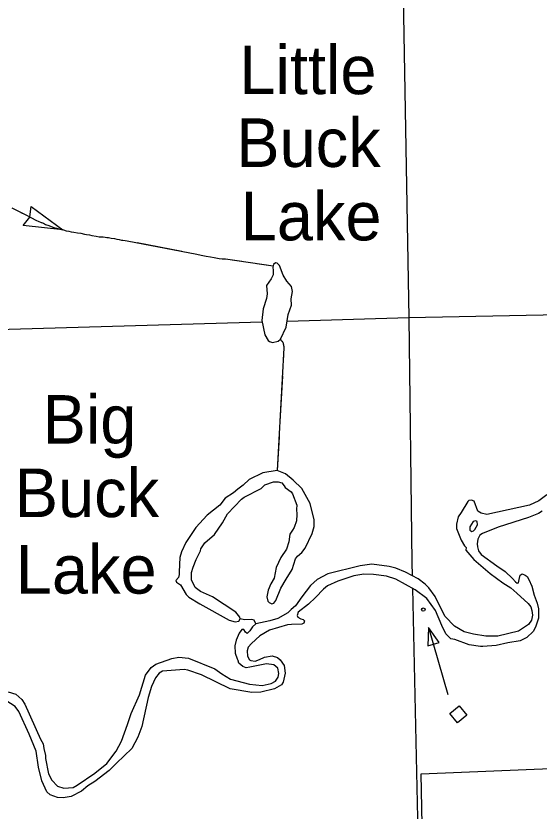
# Model space of a CAD drawing. Extents: x 1084508 to 1142749, y 1057638 to 1093403.
# Drawn here: x 1086600 to 1088029, y 1078847 to 1081018 of the extents above; entities that cross this region are included whole.
import ezdxf

# ---------------------------------------------------------------- set-up
doc = ezdxf.new("R2010")
doc.units = 0
for name, color, linetype in [('Level 35', 7, 'Continuous'), ('Level 43', 7, 'Continuous'), ('Level 5', 7, 'Continuous'), ('Level 56', 7, 'Continuous'), ('Level 7', 7, 'Continuous'), ('Level 9', 7, 'Continuous')]:
    doc.layers.add(name, color=color, linetype=linetype)

msp = doc.modelspace()

# ---------------------------------------------------------------- linework, layer by layer
at = {"layer": 'Level 35'}
for points in [[(1087303.2, 1080335.8), (1087301.5, 1080332), (1087302.5, 1080322.9), (1087302.4, 1080311.2), (1087296.9, 1080299.9), (1087284.8, 1080282.3), (1087286.5, 1080259.6), (1087284.5, 1080246.9), (1087275.8, 1080218.1), (1087272.2, 1080186.4), (1087279.6, 1080147.6), (1087288.8, 1080131.6), (1087292.7, 1080129.3), (1087300.7, 1080126.5), (1087316.3, 1080129.7), (1087322.6, 1080135.1)], [(1087322.6, 1080135.1), (1087338.4, 1080168.3), (1087343.8, 1080202.9), (1087353, 1080228), (1087351.6, 1080245.6), (1087355.5, 1080265.3), (1087352.9, 1080279.1), (1087340, 1080293.7), (1087330.1, 1080310.2), (1087320.1, 1080336.9), (1087313.9, 1080342.9), (1087308.8, 1080344), (1087303.7, 1080339), (1087303.2, 1080335.8)], [(1087313.9, 1079777.4), (1087274.6, 1079770.6), (1087237.6, 1079752.8), (1087220.8, 1079736.6), (1087206.1, 1079726.4), (1087194.6, 1079716.4), (1087171.4, 1079701.5), (1087156.8, 1079682.5), (1087122.5, 1079655.4), (1087091.9, 1079621.5), (1087064.5, 1079580.1), (1087052.1, 1079554.6), (1087048.4, 1079539.9), (1087045.8, 1079500.1), (1087046.1, 1079493.1), (1087044.6, 1079484.9), (1087037.4, 1079477), (1087038.9, 1079472), (1087049.9, 1079464.9), (1087065.5, 1079438.8), (1087072.5, 1079431.2)], [(1087338.7, 1079480.4), (1087354.5, 1079507), (1087363.9, 1079535.5), (1087369.2, 1079543.3), (1087380.7, 1079553.3), (1087390.2, 1079565.1), (1087409.5, 1079604.8), (1087415.2, 1079624), (1087415, 1079642.3), (1087403.9, 1079686.9), (1087380.7, 1079727.5), (1087357.6, 1079751), (1087336.1, 1079768), (1087313.9, 1079777.4)], [(1087223.5, 1079704.5), (1087269.6, 1079728.1), (1087279.9, 1079737.7), (1087303.4, 1079746), (1087316.9, 1079746.3), (1087326.5, 1079743), (1087333.1, 1079735.4), (1087335.9, 1079730.5), (1087351.8, 1079718.6), (1087355.8, 1079713.1), (1087367.3, 1079682.1), (1087366.5, 1079671.3), (1087367.8, 1079656.8), (1087366.1, 1079639.4), (1087360, 1079621.1), (1087355.3, 1079614.6), (1087348.2, 1079603.2), (1087345.4, 1079582), (1087339.4, 1079562.1), (1087323.4, 1079539.9), (1087311.4, 1079511.9), (1087305.2, 1079483.6), (1087296.4, 1079468), (1087289.1, 1079450), (1087285.8, 1079432.2), (1087288.5, 1079420.3), (1087291.8, 1079416.7), (1087299.2, 1079413.2), (1087304.2, 1079415), (1087310.4, 1079422.6), (1087324, 1079456), (1087338.7, 1079480.4)], [(1087255.5, 1079358.2), (1087250.9, 1079369), (1087244.8, 1079370.3), (1087224.7, 1079369.4), (1087212.7, 1079372), (1087212.1, 1079376.7), (1087200.8, 1079390.4), (1087137.6, 1079432), (1087104.8, 1079447.2), (1087089.9, 1079457.3), (1087080.1, 1079478.9), (1087079.8, 1079498.8), (1087084.2, 1079513.2), (1087092.4, 1079534.1), (1087104.5, 1079557.7), (1087105.2, 1079563.1), (1087116.4, 1079580), (1087142.5, 1079602.3), (1087164.3, 1079634.3), (1087178.3, 1079658.9), (1087216.5, 1079699.1), (1087223.5, 1079704.5)], [(1087072.5, 1079431.2), (1087102.3, 1079412.7), (1087182.3, 1079368.7), (1087198.6, 1079364.1), (1087208.9, 1079365.5), (1087212.7, 1079372)]]:
    msp.add_lwpolyline(points, dxfattribs=at)
at = {"layer": 'Level 43'}
for p, q in [((1086638.1, 1080469), (1086641.8, 1080497.4)), ((1086641.8, 1080497.7), (1086728.3, 1080433.7)), ((1086620.5, 1080445.8), (1086638, 1080468.6)), ((1086728.4, 1080433.7), (1086620.4, 1080445.8)), ((1086620.4, 1080445.8), (1086620.5, 1080445.8))]:
    msp.add_line(p, q, dxfattribs=at)
for points in [[(1086589.7, 1080494.3), (1086609.3, 1080483.6), (1086626.1, 1080475.5), (1086642.8, 1080466.5), (1086655.1, 1080460.4), (1086663.4, 1080456.7), (1086667.9, 1080454.4), (1086675.6, 1080451.9), (1086681.1, 1080448.7), (1086690, 1080445.6), (1086696.4, 1080443.4), (1086704.4, 1080440.6), (1086711.4, 1080438.4), (1086721.6, 1080435.4), (1086730.2, 1080433.6), (1086737.2, 1080431.4), (1086744.6, 1080429.8), (1086750.9, 1080428.8), (1086758.5, 1080427.3), (1086768.6, 1080425.9), (1086777.5, 1080424.4), (1086788, 1080421.7), (1086793.1, 1080421.3), (1086801.6, 1080419.8), (1086807.4, 1080418.2), (1086819.4, 1080416.2), (1086827.7, 1080414.7), (1086834.3, 1080414.4), (1086838.7, 1080414.6), (1086843.7, 1080414.2), (1086848.8, 1080413.4), (1086853.6, 1080412.7), (1086860.6, 1080410.8), (1086869.4, 1080410), (1086876.4, 1080408.1), (1086882.1, 1080407.1), (1086888.5, 1080406.1), (1086892.3, 1080406), (1086898.9, 1080404.7), (1086904.3, 1080404.3), (1087094.4, 1080367.6), (1087106.2, 1080365), (1087119.8, 1080362.4), (1087131.6, 1080360.1), (1087142, 1080358.7), (1087155.7, 1080355.9), (1087163.9, 1080355), (1087172.7, 1080354.8), (1087303.2, 1080335.8)], [(1086613.6, 1080481.5), (1086626.1, 1080475.5), (1086642.8, 1080466.5), (1086655.1, 1080460.4), (1086663.4, 1080456.7), (1086667.9, 1080454.4), (1086669.3, 1080453.9)], [(1086669.3, 1080453.9), (1086675.6, 1080451.9), (1086681.1, 1080448.7), (1086690, 1080445.6), (1086696.4, 1080443.4), (1086704.4, 1080440.6), (1086711.4, 1080438.4), (1086721.6, 1080435.4), (1086728, 1080434)], [(1086768.5, 1080425.9), (1086768.6, 1080425.9), (1086777.5, 1080424.4), (1086788, 1080421.7), (1086793.1, 1080421.3), (1086801.6, 1080419.8), (1086807.4, 1080418.2), (1086819.4, 1080416.2), (1086827.7, 1080414.7), (1086834.3, 1080414.4), (1086838.7, 1080414.6), (1086843.7, 1080414.2), (1086848.8, 1080413.4), (1086853.6, 1080412.7), (1086860.6, 1080410.8), (1086869.4, 1080410), (1086876.4, 1080408.1), (1086882.1, 1080407.1), (1086888.5, 1080406.1), (1086890.9, 1080406)], [(1086931.7, 1080399), (1087053.7, 1080375.5)], [(1087094.4, 1080367.6), (1087094.4, 1080367.6), (1087106.2, 1080365), (1087119.8, 1080362.4), (1087131.6, 1080360.1), (1087142, 1080358.7), (1087155.7, 1080355.9), (1087163.9, 1080355), (1087172.7, 1080354.8), (1087217, 1080348.3)], [(1087258, 1080342.4), (1087303.2, 1080335.8)], [(1087322.6, 1080135.1), (1087324, 1080133.6), (1087325, 1080132.3), (1087325, 1080132), (1087325.6, 1080131.4), (1087326.3, 1080130.2), (1087327.6, 1080129.6), (1087328.3, 1080128.1), (1087329, 1080126.8), (1087329.7, 1080125.3), (1087330.4, 1080122.8), (1087331.2, 1080120.3), (1087331.3, 1080118.4), (1087332, 1080115.3), (1087332.2, 1080111.5), (1087313.9, 1079777.4)], [(1087322.6, 1080135.1), (1087324, 1080133.6), (1087325, 1080132.3), (1087325, 1080132), (1087325.6, 1080131.4), (1087326.3, 1080130.2), (1087327.6, 1080129.6), (1087328.3, 1080128.1), (1087329, 1080126.8), (1087329.7, 1080125.3), (1087330.4, 1080122.8), (1087331.2, 1080120.3), (1087331.3, 1080118.4), (1087332, 1080115.3), (1087332.2, 1080111.5), (1087330.2, 1080075.9)], [(1087328, 1080034.6), (1087321.2, 1079910.4)], [(1087318.9, 1079869.1), (1087313.9, 1079777.4)]]:
    msp.add_lwpolyline(points, dxfattribs=at)
at = {"layer": 'Level 5'}
msp.add_line((1087273, 1080182.1), (1085752.4, 1080138.1), dxfattribs=at)
for points in [[(1087592.5, 1084319.5), (1087602.1, 1083492.6), (1087618.6, 1082806.7), (1087643.8, 1081844.1), (1087673, 1080193.7), (1087681.8, 1079526.1)], [(1088360.3, 1080207.8), (1087673, 1080193.7), (1087340.9, 1080184.1)], [(1087681.8, 1079526.1), (1087682.5, 1079490.6)], [(1087683.3, 1079455.6), (1087701.8, 1078618.5)]]:
    msp.add_lwpolyline(points, dxfattribs=at)
at = {"layer": 'Level 56'}
for points in [[(1087725, 1079298.3), (1087755.7, 1079307.2), (1087727, 1079348.8)], [(1087785.3, 1079113.6), (1087810.6, 1079134.3), (1087831.4, 1079108.9), (1087806.1, 1079088.2)]]:
    msp.add_lwpolyline(points, close=True, dxfattribs=at)
msp.add_lwpolyline([(1087727, 1079348.8), (1087780, 1079166)], dxfattribs=at)
msp.add_circle((1087712.8, 1079397.5), 4.71, dxfattribs=at)
at = {"layer": 'Level 7'}
msp.add_lwpolyline([(1087713.6, 1078624.6), (1087706.6, 1078948.8), (1088170.3, 1078968.6), (1088170.5, 1079039.2), (1088369.3, 1079043.8), (1088402, 1078976.5), (1088431.3, 1078977.5)], dxfattribs=at)
at = {"layer": 'Level 9'}
for points in [[(1088050.4, 1079710.2), (1088028.1, 1079694.7), (1088002.8, 1079682.8), (1087886.4, 1079656.6), (1087871.1, 1079661), (1087862, 1079666.3), (1087851.3, 1079693.5), (1087844.3, 1079696.4), (1087837.4, 1079694.8), (1087834.4, 1079692.1), (1087816.3, 1079662.3), (1087808, 1079650.8), (1087803.2, 1079630.7), (1087803.7, 1079618.8), (1087815.9, 1079586.5), (1087825.4, 1079571.2), (1087830, 1079567), (1087829.1, 1079560), (1087850.7, 1079534.5), (1087894.9, 1079496.1), (1087930, 1079470.6), (1087952, 1079456.4), (1087967.8, 1079442), (1087999.2, 1079414.4), (1088006.3, 1079404.6), (1088008.9, 1079394.7)], [(1088037, 1079666.1), (1088027.2, 1079659.3), (1088000, 1079648.6), (1087916.9, 1079622.1), (1087874.2, 1079604.7), (1087867.5, 1079600.2), (1087861.7, 1079589.9), (1087859.7, 1079577.2), (1087860.5, 1079568.4), (1087863.1, 1079557.8), (1087870.5, 1079547.4), (1087913.4, 1079517.1), (1087936.1, 1079501.8), (1087956.5, 1079482.2), (1087964.5, 1079473.4), (1087969, 1079469.8), (1087972.2, 1079470), (1087974.9, 1079479.6), (1087977.5, 1079491.7), (1087982.4, 1079494.7), (1087991, 1079491.7), (1087996.3, 1079487.5), (1088000.7, 1079479.8)], [(1087853.3, 1079615.7), (1087860.9, 1079628.3), (1087859.6, 1079637.8), (1087856.3, 1079640.1), (1087848.9, 1079637.7), (1087839.8, 1079623), (1087839.8, 1079614.4), (1087845.6, 1079610.9), (1087850, 1079612.1), (1087853.3, 1079615.7)], [(1088008.9, 1079394.7), (1088010.8, 1079382.1), (1088008.2, 1079368.8), (1087999.6, 1079357), (1087986.5, 1079347.6), (1087972.4, 1079338.7), (1087916.1, 1079324.8), (1087883.7, 1079325.2), (1087849.5, 1079330.5), (1087824.6, 1079337), (1087798.2, 1079352.2), (1087772.4, 1079378.8), (1087759, 1079404.7), (1087745.4, 1079433.1), (1087728, 1079457.2), (1087717.5, 1079467.1), (1087698.9, 1079481.1), (1087664.4, 1079499.4), (1087637.5, 1079510.2), (1087619.9, 1079515.4), (1087572.2, 1079521.1), (1087540.3, 1079517.1), (1087451.9, 1079494.7), (1087422.7, 1079479.5), (1087404.6, 1079462.9), (1087380.8, 1079432.1), (1087364, 1079408), (1087351.9, 1079397.3), (1087342.8, 1079389)], [(1088000.7, 1079479.8), (1088009.1, 1079461.6), (1088015.2, 1079437.2), (1088023.8, 1079414.9), (1088027.3, 1079399.3), (1088026.9, 1079374), (1088019.5, 1079349.1), (1088012.8, 1079337.7), (1087995.3, 1079321.1), (1087976.8, 1079311.8), (1087943.7, 1079307.1), (1087911.9, 1079299.3), (1087875.5, 1079297), (1087869.3, 1079296.7), (1087838.2, 1079301.6), (1087799.2, 1079315.6), (1087787.5, 1079317.6), (1087773.9, 1079331.5), (1087763.5, 1079354.4), (1087746.2, 1079394.9), (1087722.4, 1079427.6), (1087690.5, 1079451.4), (1087637.3, 1079480.5), (1087612.7, 1079488.2), (1087576.6, 1079493.5), (1087550.4, 1079494.2), (1087522.6, 1079489.4), (1087479.5, 1079475.1), (1087451.5, 1079461.9), (1087440.6, 1079453.2)], [(1087440.6, 1079453.2), (1087418, 1079430.7), (1087399, 1079412.1), (1087371, 1079390.6), (1087368.3, 1079381.7), (1087370.4, 1079377), (1087378.8, 1079372.1), (1087384.8, 1079370.8), (1087388.2, 1079366.5), (1087386.2, 1079360.7), (1087381.3, 1079357.4), (1087353, 1079357), (1087341.8, 1079355.9), (1087292.7, 1079341.6), (1087266.4, 1079325.9), (1087243.4, 1079304.6), (1087235, 1079294.5), (1087232, 1079284.6), (1087232.4, 1079270.1), (1087237.8, 1079260.5), (1087241.4, 1079258.5), (1087253.7, 1079257.1), (1087265.8, 1079261.2), (1087279, 1079267.8), (1087299.7, 1079271.2), (1087314.6, 1079266.9), (1087322.2, 1079260.3)], [(1087342.8, 1079389), (1087315.8, 1079373), (1087293.5, 1079366.3), (1087255.5, 1079358.2)], [(1087255.5, 1079358.2), (1087246.4, 1079350.2), (1087239.3, 1079339.5), (1087231.4, 1079332.5), (1087227.2, 1079336.1), (1087222.8, 1079343.5), (1087217.1, 1079343.2), (1087210, 1079333.4), (1087202.1, 1079313.8), (1087198.4, 1079298.2), (1087199.3, 1079278.3), (1087204.1, 1079263.1), (1087206.8, 1079257.5)], [(1086689.1, 1078949.5), (1086698.6, 1078931.9), (1086714, 1078915.8), (1086731.5, 1078910.2), (1086756.6, 1078911.8), (1086767.3, 1078918.5), (1086815.8, 1078950.7), (1086848.7, 1078977.5), (1086874.4, 1079011), (1086888.8, 1079038), (1086904.9, 1079083.4), (1086914.7, 1079114), (1086937.6, 1079164.4), (1086954.4, 1079218.7), (1086969.9, 1079239.1), (1086982.1, 1079248.8), (1087026.2, 1079264.3), (1087045.2, 1079267.9), (1087071.5, 1079264.5), (1087143.6, 1079235.5), (1087162.7, 1079222.4)], [(1087322.2, 1079260.3), (1087333.2, 1079244.8), (1087335.2, 1079223.7), (1087330.2, 1079199.3), (1087325.2, 1079191.8), (1087306.7, 1079180.7), (1087269, 1079171.7), (1087244.9, 1079170.7), (1087185.4, 1079180.7), (1087106.9, 1079219.3), (1087070.2, 1079232.3), (1087060.1, 1079233.5), (1087000.2, 1079229.6), (1086991.6, 1079224.2), (1086981.1, 1079211.5), (1086970.7, 1079187.8), (1086961.5, 1079157.8), (1086944.4, 1079078.3), (1086933, 1079049.2)], [(1087162.7, 1079222.4), (1087186.5, 1079207.2), (1087238.3, 1079193.5), (1087272.7, 1079189.8), (1087297.7, 1079195.5), (1087309.1, 1079201.9), (1087316.2, 1079212.6), (1087318, 1079223.4), (1087315.9, 1079237.2), (1087304.8, 1079246.2), (1087284.9, 1079249.5), (1087239, 1079240.5), (1087228.7, 1079238.8), (1087220.4, 1079242), (1087209.4, 1079251.3), (1087206.8, 1079257.5)], [(1086579.5, 1079173.2), (1086600.5, 1079166.7), (1086616.2, 1079151.9), (1086624.8, 1079139), (1086667.5, 1079043.9), (1086674.6, 1079030.9), (1086676.7, 1079018.4), (1086680.9, 1078999.6), (1086681.5, 1078991.1), (1086689.1, 1078949.5)], [(1086933, 1079049.2), (1086916.9, 1079018.6), (1086875.1, 1078977.9), (1086855.1, 1078958.2), (1086816, 1078928.3), (1086797, 1078916.8), (1086779.6, 1078902), (1086751.2, 1078887.6), (1086729.7, 1078884), (1086714.3, 1078884.3), (1086693.5, 1078891.7), (1086685.1, 1078899.9), (1086671.6, 1078929.6), (1086661.7, 1078967), (1086655.6, 1079011.3), (1086636.2, 1079057.8), (1086608, 1079119.1), (1086598.3, 1079133.2), (1086572.6, 1079149.6), (1086557.7, 1079150.9), (1086548, 1079149.5), (1086543.4, 1079146.8)]]:
    msp.add_lwpolyline(points, dxfattribs=at)

# ---------------------------------------------------------------- texts
at = {"layer": 'Level 35'}
for s, p in [('Little', (1087210.5, 1080804.2)), ('Buck', (1087202.1, 1080605.5)), ('Lake', (1087214.3, 1080405.1)), ('Big', (1086673.2, 1079850.2)), ('Buck', (1086597.2, 1079649.8)), ('Lake', (1086600.2, 1079441))]:
    msp.add_text(s, height=132.58, dxfattribs=at).set_placement(p)

doc.saveas('drawing.dxf')
